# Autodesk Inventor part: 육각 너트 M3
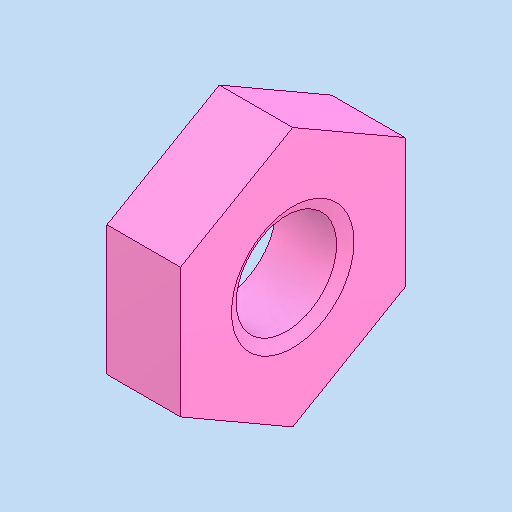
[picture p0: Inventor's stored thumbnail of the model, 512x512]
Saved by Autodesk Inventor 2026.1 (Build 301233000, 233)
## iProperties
Created: 2025-09
Part Number: 육각 너트 M3
Material: 강철, 연강
Description: 6각 너트 및 6각 가는 너트 - 모따기 안된
Document SubType Name: Modeling
Designer: PC-30
Density: 7.85 g/cm^3
Appearance: 기본값
Author: jhkim
Sending System: Autodesk Inventor 2026
Preprocessor: ST-DEVELOPER v20.1
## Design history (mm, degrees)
feature "Solid1"
node "솔리드1"
